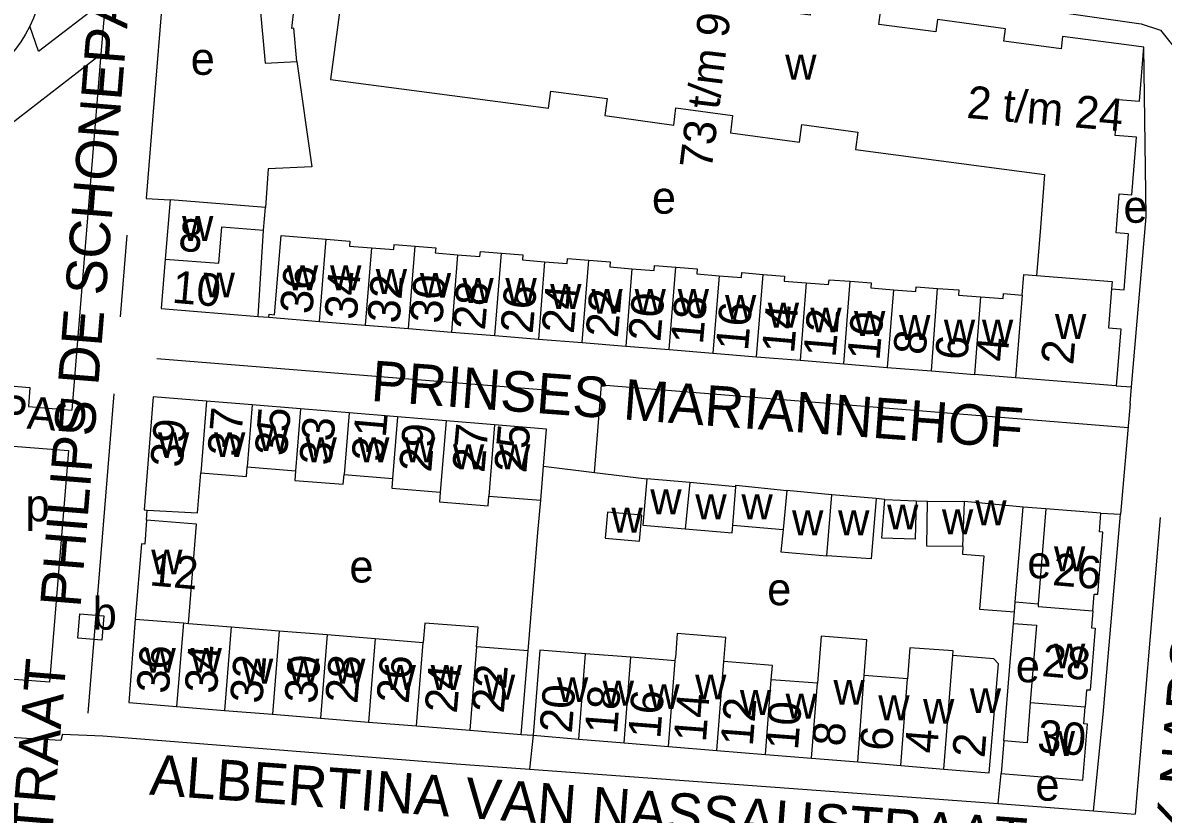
# Model space of a CAD drawing. Extents: x 159261 to 160849, y 382514 to 384534.
# Drawn here: x 160446.5 to 160587.3, y 383197.9 to 383295.6 of the extents above; entities that cross this region are included whole.
import ezdxf

# ---------------------------------------------------------------- set-up
doc = ezdxf.new("R2010")
doc.units = 0
for name, color, linetype in [('BLT_Basislijn', 7, 'Continuous'), ('BLT_Bebouwing', 7, 'Continuous'), ('BLT_Centroide', 7, 'Continuous'), ('BLT_Huisnummer', 7, 'Continuous'), ('BLT_Huisnummer_ tussenligend', 7, 'Continuous'), ('BLT_Huisnummer_reeks', 7, 'Continuous'), ('BLT_Onderverdeling_panden', 7, 'Continuous'), ('BLT_Straatnaam', 7, 'Continuous'), ('BLT_Straatnaam_verkleind', 7, 'Continuous')]:
    doc.layers.add(name, color=color, linetype=linetype)

msp = doc.modelspace()

# ---------------------------------------------------------------- linework, layer by layer
at = {"layer": 'BLT_Basislijn'}
for p, q in [((160464.45, 383307.53), (160462.73, 383286.15)), ((160448.46, 383292.15), (160456.71, 383298.51)), ((160456.71, 383298.51), (160456.16, 383291.77)), ((160568.13, 383297.86), (160584.55, 383295.5)), ((160448.46, 383292.15), (160447.37, 383295.2)), ((160430.9, 383272.29), (160456.16, 383291.77)), ((160456.16, 383291.77), (160452.56, 383247.83)), ((160480.34, 383290.85), (160482.21, 383277.84)), ((160462.73, 383286.15), (160461.75, 383273.95)), ((160461.75, 383273.95), (160464.7, 383273.78)), ((160458.56, 383259.32), (160459.39, 383269.42)), ((160475.56, 383259.39), (160476.89, 383259.28)), ((160463.05, 383254.2), (160511.51, 383250.27)), ((160581.48, 383250.8), (160583.37, 383250.69)), ((160583.19, 383248.63), (160583.37, 383250.69)), ((160454.57, 383210.42), (160457.79, 383249.85)), ((160447.21, 383248.25), (160452.56, 383247.83)), ((160583.19, 383248.63), (160582.01, 383234.97)), ((160445.32, 383243.38), (160452.15, 383242.84)), ((160452.15, 383242.84), (160449.81, 383214.26)), ((160510.78, 383240.9), (160517.07, 383240.13)), ((160517.07, 383240.13), (160523.53, 383239.33)), ((160510.09, 383232.7), (160510.44, 383236.7)), ((160552.91, 383236.79), (160551.86, 383236.9)), ((160556.8, 383236.62), (160558.18, 383236.59)), ((160461.8, 383234.23), (160461.87, 383235.47)), ((160572.8, 383235.64), (160569.98, 383235.85)), ((160579.6, 383235.09), (160582.01, 383234.97)), ((160586.91, 383234.56), (160583.82, 383197.95)), ((160508.89, 383218.1), (160510.09, 383232.7)), ((160449.81, 383214.26), (160444.34, 383214.65)), ((160446.96, 383207.29), (160443.81, 383207.5)), ((160451.4, 383207.83), (160456.41, 383207.6)), ((160508.02, 383207.79), (160509.5, 383207.69)), ((160509.5, 383207.69), (160509.04, 383203.52)), ((160509.04, 383203.52), (160566.93, 383199.26)), ((160566.93, 383199.26), (160567.3, 383202.95)), ((160566.93, 383199.26), (160578.66, 383198.35)), ((160578.66, 383198.35), (160583.82, 383197.95))]:
    msp.add_line(p, q, dxfattribs=at)
for points in [[(160448.48, 383298.32), (160448.19, 383297.25), (160447.82, 383296.21), (160447.37, 383295.2)], [(160584.55, 383295.5), (160586.95, 383294.73), (160588.92, 383292.24), (160589.56, 383290.35)], [(160447.37, 383295.2), (160446.86, 383294.22), (160446.27, 383293.28), (160445.62, 383292.38), (160444.91, 383291.54), (160444.14, 383290.75), (160443.53, 383290.2)], [(160583.37, 383250.69), (160585.18, 383271.68), (160584.88, 383292.62)], [(160482.21, 383277.84), (160476.79, 383277.6), (160476.45, 383272.82)], [(160412.58, 383255.96), (160415.4, 383253.87), (160418.04, 383253.1), (160447.4, 383250.63), (160447.21, 383248.25)], [(160517.07, 383240.13), (160517.95, 383250.95), (160582.96, 383245.67)], [(160578.66, 383198.35), (160579.88, 383210.25), (160582.01, 383234.97)], [(160567.63, 383207.01), (160568.39, 383216.72), (160568.82, 383221.5)], [(160451.4, 383207.83), (160451.19, 383207.06), (160446.96, 383207.29)], [(160456.41, 383207.6), (160500, 383204.17), (160508.54, 383203.55), (160509.04, 383203.52)]]:
    msp.add_lwpolyline(points, dxfattribs=at)
at = {"layer": 'BLT_Bebouwing'}
for p, q in [((160584.34, 383285.95), (160584.88, 383292.62)), ((160464.7, 383273.78), (160464.1, 383266.46)), ((160476.45, 383272.82), (160464.7, 383273.78)), ((160476.22, 383270.05), (160476.45, 383272.82)), ((160475.56, 383259.39), (160476.22, 383270.05)), ((160489.56, 383267.86), (160492.32, 383267.64)), ((160464.1, 383266.46), (160463.6, 383260.36)), ((160463.6, 383260.36), (160475.56, 383259.39)), ((160476.89, 383259.28), (160483.15, 383258.77)), ((160483.15, 383258.77), (160488.79, 383258.32)), ((160488.79, 383258.32), (160494.11, 383257.89)), ((160494.11, 383257.89), (160499.41, 383257.46)), ((160499.41, 383257.46), (160504.77, 383257.03)), ((160504.77, 383257.03), (160510.15, 383256.59)), ((160510.15, 383256.59), (160515.54, 383256.16)), ((160515.54, 383256.16), (160520.93, 383255.72)), ((160520.93, 383255.72), (160526.31, 383255.29)), ((160526.31, 383255.29), (160531.69, 383254.85)), ((160531.69, 383254.85), (160537.07, 383254.41)), ((160537.07, 383254.41), (160542.46, 383253.97)), ((160542.46, 383253.97), (160547.85, 383253.54)), ((160547.85, 383253.54), (160553.23, 383253.1)), ((160553.23, 383253.1), (160558.67, 383252.66)), ((160558.67, 383252.66), (160563.98, 383252.23)), ((160569.06, 383251.81), (160563.98, 383252.23)), ((160581.48, 383250.8), (160569.06, 383251.81)), ((160469.18, 383248.92), (160462.61, 383249.46)), ((160474.83, 383248.46), (160469.18, 383248.92)), ((160480.81, 383247.97), (160474.83, 383248.46)), ((160486.78, 383247.49), (160480.81, 383247.97)), ((160492.77, 383246.99), (160486.78, 383247.49)), ((160498.76, 383246.51), (160492.77, 383246.99)), ((160504.74, 383246.02), (160498.76, 383246.51)), ((160474.21, 383240.82), (160480.19, 383240.34)), ((160510.44, 383236.7), (160510.77, 383240.9)), ((160486.17, 383239.86), (160492.15, 383239.38)), ((160528.86, 383238.87), (160523.53, 383239.33)), ((160534.52, 383238.37), (160528.86, 383238.87)), ((160546.37, 383237.36), (160540.84, 383237.92)), ((160504.03, 383237.21), (160510.44, 383236.7)), ((160551.86, 383236.9), (160546.37, 383237.36)), ((160552.91, 383236.79), (160556.8, 383236.62)), ((160556.8, 383236.62), (160556.66, 383231.88)), ((160558.18, 383236.59), (160562.75, 383236.54)), ((160569.98, 383235.85), (160562.75, 383236.54)), ((160569.03, 383224.14), (160569.98, 383235.85)), ((160572.8, 383235.64), (160571.86, 383223.91)), ((160579.6, 383235.09), (160572.8, 383235.64)), ((160534.15, 383233.63), (160540.37, 383233.08)), ((160569.03, 383224.14), (160571.86, 383223.91)), ((160568.82, 383221.5), (160568.94, 383222.92)), ((160466.98, 383221.49), (160472.25, 383221.07)), ((160472.25, 383221.07), (160478.17, 383220.59)), ((160478.17, 383220.59), (160484.1, 383220.11)), ((160484.1, 383220.11), (160490.02, 383219.63)), ((160490.02, 383219.63), (160495.94, 383219.15)), ((160508.89, 383218.1), (160502.53, 383218.61)), ((160508.02, 383207.79), (160508.89, 383218.1)), ((160515.97, 383217.74), (160510.34, 383218.18)), ((160521.56, 383217.31), (160515.97, 383217.74)), ((160527.04, 383216.88), (160521.56, 383217.31)), ((160527.04, 383216.88), (160527.07, 383217.26)), ((160565.8, 383203.07), (160566.94, 383216.5)), ((160544.6, 383214.11), (160538.91, 383214.55)), ((160465.5, 383211.24), (160471.42, 383210.76)), ((160471.42, 383210.76), (160477.34, 383210.28)), ((160477.34, 383210.28), (160483.26, 383209.8)), ((160483.26, 383209.8), (160489.18, 383209.32)), ((160489.18, 383209.32), (160495.1, 383208.84)), ((160495.1, 383208.84), (160501.7, 383208.3)), ((160501.7, 383208.3), (160508.02, 383207.79)), ((160509.5, 383207.69), (160515.16, 383207.22)), ((160515.16, 383207.22), (160520.74, 383206.76)), ((160520.74, 383206.76), (160526.22, 383206.3)), ((160567.63, 383207.01), (160567.3, 383202.95)), ((160526.22, 383206.3), (160532.2, 383205.82)), ((160532.2, 383205.82), (160538.19, 383205.33)), ((160538.19, 383205.33), (160543.88, 383204.87)), ((160543.88, 383204.87), (160549.57, 383204.4)), ((160549.57, 383204.4), (160554.88, 383203.96)), ((160554.88, 383203.96), (160560.22, 383203.52)), ((160560.22, 383203.52), (160565.8, 383203.07))]:
    msp.add_line(p, q, dxfattribs=at)
for points in [[(160479.72, 383294.94), (160480.01, 383297.49), (160479.41, 383303.07), (160479.15, 383305.48)], [(160486.8, 383305.75), (160486.29, 383301.95), (160488.17, 383301.67), (160487.79, 383299.16), (160485.95, 383299.43), (160484.5, 383288.62), (160511.42, 383285.09), (160511.7, 383287.2), (160518.65, 383286.27), (160518.37, 383284.18), (160526.86, 383283.01), (160527.14, 383285.14), (160534.13, 383284.2), (160533.88, 383282.07), (160542.39, 383280.91), (160542.68, 383283.06), (160549.58, 383282.14), (160549.32, 383279.98), (160572.65, 383276.89), (160572.08, 383269.81), (160571.65, 383264.44)], [(160584.88, 383292.62), (160583.35, 383292.83), (160574.87, 383293.96), (160574.67, 383292.43), (160567.62, 383293.38), (160567.83, 383294.9), (160559.42, 383296.03), (160559.21, 383294.5), (160552.17, 383295.44), (160552.37, 383296.97), (160543.93, 383298.1), (160543.72, 383296.57), (160536.68, 383297.53), (160536.89, 383299.04), (160528.46, 383300.17), (160528.26, 383298.66), (160521.21, 383299.6), (160521.42, 383301.11), (160512.99, 383302.24), (160512.8, 383300.72), (160505.75, 383301.67), (160505.98, 383303.34), (160486.8, 383305.75)], [(160475.77, 383297.83), (160476.44, 383290.64), (160480.34, 383290.85)], [(160480.34, 383290.85), (160479.96, 383294.98), (160479.72, 383294.94)], [(160580.91, 383262.8), (160582.45, 383262.67), (160583.01, 383269.59), (160581.47, 383269.71), (160581.86, 383274.52), (160583.4, 383274.39), (160583.98, 383281.52), (160582.44, 383281.64), (160581.35, 383281.73), (160581.71, 383286.18), (160582.8, 383286.08), (160584.34, 383285.95)], [(160476.89, 383259.28), (160476.93, 383259.65), (160477.59, 383259.6), (160478.39, 383269.38), (160483.97, 383268.93)], [(160483.97, 383268.93), (160486.87, 383268.69), (160486.82, 383268.08), (160489.56, 383267.86)], [(160492.32, 383267.64), (160492.37, 383268.26), (160494.93, 383268.06)], [(160494.93, 383268.06), (160497.48, 383267.85), (160497.43, 383267.22), (160500.18, 383267)], [(160500.18, 383267), (160502.94, 383266.78), (160503, 383267.41), (160505.62, 383267.2)], [(160505.62, 383267.2), (160508.23, 383266.98), (160508.18, 383266.36), (160510.92, 383266.14)], [(160510.92, 383266.14), (160513.69, 383265.92), (160513.74, 383266.54), (160516.38, 383266.33)], [(160516.38, 383266.33), (160519.02, 383266.11), (160518.97, 383265.49), (160521.7, 383265.27)], [(160521.7, 383265.27), (160524.45, 383265.05), (160524.5, 383265.67), (160527.13, 383265.46)], [(160527.13, 383265.46), (160529.76, 383265.25), (160529.71, 383264.63), (160532.46, 383264.41)], [(160532.46, 383264.41), (160535.22, 383264.18), (160535.26, 383264.8), (160537.9, 383264.58)], [(160537.9, 383264.58), (160540.53, 383264.37), (160540.48, 383263.76), (160543.23, 383263.54)], [(160569.89, 383262.01), (160570.1, 383264.57), (160571.65, 383264.44)], [(160543.23, 383263.54), (160545.98, 383263.32), (160546.03, 383263.92), (160548.64, 383263.72)], [(160548.64, 383263.72), (160551.24, 383263.52), (160551.2, 383262.9), (160554, 383262.67)], [(160554, 383262.67), (160556.75, 383262.45), (160556.8, 383263.04), (160559.42, 383262.85)], [(160559.42, 383262.85), (160562.05, 383262.66), (160562, 383262.03), (160564.75, 383261.81)], [(160564.75, 383261.81), (160567.52, 383261.58), (160567.57, 383262.2), (160569.89, 383262.01)], [(160580.91, 383262.8), (160580.52, 383258), (160582.06, 383257.87), (160581.48, 383250.8)], [(160462.61, 383249.46), (160461.49, 383235.5), (160461.87, 383235.47)], [(160510.78, 383240.9), (160511.15, 383245.49), (160504.74, 383246.02)], [(160468.47, 383240.08), (160474.12, 383239.62), (160474.21, 383240.82)], [(160461.87, 383235.47), (160468.07, 383235.13), (160468.47, 383240.08)], [(160480.19, 383240.34), (160480.1, 383239.15), (160486.07, 383238.67), (160486.17, 383239.86)], [(160492.15, 383239.38), (160492.05, 383238.18), (160498.05, 383237.69)], [(160523.53, 383239.33), (160523.05, 383233.64), (160528.28, 383233.18)], [(160498.05, 383237.69), (160497.95, 383236.5), (160503.94, 383236.02), (160504.03, 383237.21)], [(160534.52, 383238.37), (160534.53, 383238.55), (160540.84, 383237.92)], [(160551.86, 383236.9), (160551.22, 383229.46), (160545.76, 383229.82)], [(160556.66, 383231.88), (160552.57, 383232), (160552.91, 383236.79)], [(160562.57, 383230.99), (160558.12, 383231.04), (160558.18, 383236.59)], [(160578.61, 383223.03), (160578.78, 383225.12), (160579.23, 383225.09), (160579.85, 383232.74), (160579.41, 383232.78), (160579.6, 383235.09)], [(160461.8, 383234.23), (160461.56, 383231.27), (160461.15, 383231.3), (160460.4, 383222.03)], [(160466.98, 383221.49), (160467.96, 383233.74), (160461.8, 383234.23)], [(160528.28, 383233.18), (160534.08, 383232.66), (160534.15, 383233.63)], [(160540.37, 383233.08), (160540.1, 383230.32), (160545.76, 383229.82)], [(160562.57, 383230.99), (160562.49, 383230.03), (160565.15, 383229.82), (160564.62, 383223.27), (160568.94, 383222.92)], [(160578.61, 383223.03), (160578.44, 383220.94), (160578.89, 383220.9), (160578.26, 383213.24), (160577.82, 383213.27), (160577.65, 383211.18)], [(160460.4, 383222.03), (160459.58, 383211.72), (160465.5, 383211.24)], [(160502.53, 383218.61), (160502.72, 383221.02), (160496.13, 383221.54), (160495.94, 383219.15)], [(160568.82, 383221.5), (160571.64, 383221.27), (160570.88, 383211.74)], [(160533.05, 383216.78), (160533.29, 383219.77), (160527.3, 383220.24), (160527.07, 383217.26)], [(160550.38, 383215.07), (160550.72, 383219.47), (160545.05, 383219.91), (160544.6, 383214.11)], [(160510.34, 383218.18), (160509.5, 383207.69)], [(160561.3, 383217.54), (160561.35, 383218.09), (160556.01, 383218.5), (160555.71, 383214.65)], [(160538.91, 383214.55), (160539.04, 383216.29), (160533.05, 383216.78)], [(160566.94, 383216.5), (160566.39, 383217.14), (160561.3, 383217.54)], [(160555.71, 383214.65), (160550.38, 383215.07)], [(160567.3, 383202.95), (160577.36, 383202.14), (160577.92, 383209.05), (160577.48, 383209.09), (160577.65, 383211.18)], [(160570.88, 383211.74), (160570.48, 383206.77), (160567.63, 383207.01)]]:
    msp.add_lwpolyline(points, dxfattribs=at)
for points in [[(160522.92, 383234.86), (160518.67, 383235.24), (160518.38, 383232.03), (160522.63, 383231.65)], [(160453.56, 383222.67), (160456.5, 383222.42), (160456.25, 383219.44), (160453.31, 383219.68)]]:
    msp.add_lwpolyline(points, close=True, dxfattribs=at)
at = {"layer": 'BLT_Onderverdeling_panden'}
for p, q in [((160483.15, 383258.77), (160483.97, 383268.93)), ((160489.56, 383267.86), (160488.79, 383258.32)), ((160494.11, 383257.89), (160494.93, 383268.06)), ((160504.77, 383257.03), (160505.62, 383267.2)), ((160500.18, 383267), (160499.41, 383257.46)), ((160510.92, 383266.14), (160510.15, 383256.59)), ((160515.54, 383256.16), (160516.38, 383266.33)), ((160521.7, 383265.27), (160520.93, 383255.72)), ((160526.31, 383255.29), (160527.13, 383265.46)), ((160532.46, 383264.41), (160531.69, 383254.85)), ((160537.07, 383254.41), (160537.9, 383264.58)), ((160543.23, 383263.54), (160542.46, 383253.97)), ((160547.85, 383253.54), (160548.64, 383263.72)), ((160554, 383262.67), (160553.23, 383253.1)), ((160558.67, 383252.66), (160559.42, 383262.85)), ((160564.75, 383261.81), (160563.98, 383252.23)), ((160569.89, 383262.01), (160569.06, 383251.81)), ((160469.18, 383248.92), (160468.47, 383240.08)), ((160474.83, 383248.46), (160474.21, 383240.82)), ((160480.81, 383247.97), (160480.19, 383240.34)), ((160486.78, 383247.49), (160486.17, 383239.86)), ((160492.77, 383246.99), (160492.15, 383239.38)), ((160498.76, 383246.51), (160498.05, 383237.69)), ((160504.74, 383246.02), (160504.03, 383237.21)), ((160528.86, 383238.87), (160528.28, 383233.18)), ((160534.15, 383233.63), (160534.52, 383238.37)), ((160540.84, 383237.92), (160540.37, 383233.08)), ((160545.76, 383229.82), (160546.37, 383237.36)), ((160562.57, 383230.99), (160562.75, 383236.54)), ((160568.94, 383222.92), (160569.03, 383224.14)), ((160460.4, 383222.03), (160466.33, 383221.55)), ((160466.33, 383221.55), (160465.5, 383211.24)), ((160466.33, 383221.55), (160466.98, 383221.49)), ((160472.25, 383221.07), (160471.42, 383210.76)), ((160478.17, 383220.59), (160477.34, 383210.28)), ((160484.1, 383220.11), (160483.26, 383209.8)), ((160490.02, 383219.63), (160489.18, 383209.32)), ((160495.1, 383208.84), (160495.94, 383219.15)), ((160502.53, 383218.61), (160501.7, 383208.3)), ((160515.16, 383207.22), (160515.97, 383217.74)), ((160520.74, 383206.76), (160521.56, 383217.31)), ((160526.22, 383206.3), (160527.04, 383216.88)), ((160532.2, 383205.82), (160533.05, 383216.78)), ((160560.22, 383203.52), (160561.3, 383217.54)), ((160549.57, 383204.4), (160550.38, 383215.07)), ((160538.19, 383205.33), (160538.91, 383214.55)), ((160543.88, 383204.87), (160544.6, 383214.11)), ((160554.88, 383203.96), (160555.71, 383214.65)), ((160570.88, 383211.74), (160577.65, 383211.18))]:
    msp.add_line(p, q, dxfattribs=at)
for points in [[(160464.1, 383266.46), (160470.71, 383265.98), (160471.06, 383270.45), (160476.22, 383270.05)], [(160571.65, 383264.44), (160580.98, 383263.69), (160580.91, 383262.8)], [(160571.86, 383223.91), (160571.83, 383223.58), (160578.61, 383223.03)]]:
    msp.add_lwpolyline(points, dxfattribs=at)

# ---------------------------------------------------------------- texts
at = {"layer": 'BLT_Centroide'}
for s, p in [('e', (160467.24, 383289.21)), ('w', (160540.62, 383288.63)), ('e', (160524.17, 383272.07)), ('e', (160582.38, 383270.95)), ('w', (160466.17, 383268.71)), ('w', (160468.83, 383261.73)), ('w', (160479.11, 383262.61)), ('w', (160484.44, 383262.61)), ('w', (160490.08, 383262.17)), ('w', (160495.52, 383261.69)), ('w', (160500.77, 383261.04)), ('w', (160506.09, 383261.04)), ('w', (160511.61, 383260.32)), ('w', (160516.7, 383259.71)), ('w', (160522.03, 383259.71)), ('w', (160527.35, 383259.71)), ('w', (160533.19, 383258.98)), ('w', (160538.47, 383258.01)), ('w', (160543.72, 383257.41)), ('w', (160549.12, 383256.97)), ('w', (160554.68, 383256.48)), ('w', (160560.21, 383255.93)), ('w', (160564.91, 383255.93)), ('w', (160573.93, 383256.6)), ('w', (160463.2, 383242.02)), ('w', (160470.12, 383242.02)), ('w', (160475.48, 383242.79)), ('w', (160481.41, 383241.38)), ('w', (160487.9, 383241.38)), ('w', (160493.58, 383241.38)), ('w', (160499.61, 383240.53)), ('w', (160505.3, 383240.53)), ('w', (160523.97, 383234.96)), ('p', (160446.85, 383234.09)), ('w', (160529.53, 383234.35)), ('w', (160535.22, 383234.35)), ('w', (160553.2, 383233.1)), ('w', (160564.09, 383233.62)), ('w', (160519.17, 383232.7)), ('w', (160541.47, 383232.37)), ('w', (160547.15, 383232.37)), ('w', (160559.97, 383232.5)), ('w', (160462.36, 383227.54)), ('w', (160573.8, 383227.94)), ('e', (160486.83, 383226.54)), ('e', (160570.51, 383227.06)), ('e', (160538.4, 383223.74)), ('b', (160455.14, 383220.73)), ('w', (160461.54, 383215.4)), ('w', (160467.22, 383215.4)), ('w', (160573.8, 383215.94)), ('w', (160473.56, 383214.06)), ('w', (160479.25, 383214.06)), ('w', (160484.94, 383214.06)), ('e', (160569.09, 383214.23)), ('w', (160491.17, 383213.28)), ('w', (160496.86, 383213.28)), ('w', (160503.42, 383212.08)), ('w', (160529.5, 383212.11)), ('w', (160512.45, 383211.78)), ('w', (160518.09, 383211.34)), ('w', (160523.73, 383210.91)), ('w', (160546.58, 383211.45)), ('w', (160535.03, 383210.19)), ('w', (160540.67, 383209.75)), ('w', (160552.11, 383209.55)), ('w', (160563.41, 383210.42)), ('w', (160557.64, 383209.11)), ('w', (160572.53, 383205.13)), ('e', (160571.51, 383199.61))]:
    msp.add_text(s, height=4, dxfattribs=at).set_placement(p)
at = {"layer": 'BLT_Huisnummer'}
for s, rotation, p in [('8', 355, (160465.61, 383267.52)), ('10', 355, (160464.85, 383261.09)), ('36', 85, (160482.23, 383259.6)), ('34', 85, (160487.71, 383258.89)), ('30', 85, (160498.27, 383258.42)), ('26', 85, (160509.44, 383257.18)), ('22', 85, (160519.96, 383256.67)), ('18', 85, (160530.46, 383255.86)), ('14', 85, (160541.71, 383254.74)), ('10', 85, (160552.25, 383253.86)), ('6', 85, (160563.09, 383253.9)), ('2', 85, (160576.17, 383253.33)), ('37', 85, (160473.27, 383242.02)), ('39', 85, (160466.21, 383240.65)), ('33', 85, (160484.6, 383240.91)), ('29', 85, (160496.92, 383240.08)), ('25', 85, (160508.66, 383239.98)), ('12', 355, (160462.06, 383226.2)), ('26', 355, (160573.53, 383226.23)), ('36', 85, (160464.5, 383212.74)), ('34', 85, (160470.44, 383212.74)), ('28', 355, (160572.2, 383215)), ('30', 85, (160482.76, 383211.5)), ('26', 85, (160494.13, 383211.5)), ('22', 85, (160505.88, 383210.33)), ('20', 85.5533, (160514.28, 383207.87)), ('18', 85.5533, (160519.86, 383207.75)), ('14', 85.5528, (160530.83, 383206.77)), ('10', 85.5569, (160542.2, 383205.79)), ('30', 355, (160571.64, 383205.66)), ('6', 85.5536, (160553.81, 383205.67)), ('2', 85.554, (160565.23, 383204.82))]:
    msp.add_text(s, height=4, rotation=rotation, dxfattribs=at).set_placement(p)
at = {"layer": 'BLT_Huisnummer_ tussenligend'}
for s, rotation, p in [('32', 85, (160492.99, 383258.44)), ('28', 85, (160503.55, 383257.61)), ('24', 85, (160514.52, 383257.18)), ('20', 85, (160525.21, 383256.19)), ('16', 85, (160536.02, 383255.06)), ('12', 85, (160546.83, 383254.25)), ('8', 85, (160557.93, 383254.55)), ('4', 85, (160568.04, 383253.71)), ('35', 85, (160479.1, 383242.07)), ('31', 85, (160491.05, 383241.39)), ('27', 85, (160503.49, 383240.02)), ('32', 85, (160476.05, 383211.52)), ('28', 85, (160487.8, 383211.51)), ('24', 85, (160500.08, 383210.31)), ('16', 85.5533, (160525.2, 383207.19)), ('12', 85.5569, (160536.62, 383206.26)), ('8', 85.5536, (160547.93, 383206.23)), ('4', 85.554, (160559.36, 383205.36))]:
    msp.add_text(s, height=4, rotation=rotation, dxfattribs=at).set_placement(p)
at = {"layer": 'BLT_Huisnummer_reeks'}
for s, rotation, p in [('73 t/m 95c', 83, (160531.54, 383277.45)), ('2 t/m 24', 355, (160562.93, 383283.9))]:
    msp.add_text(s, height=4, rotation=rotation, dxfattribs=at).set_placement(p)
at = {"layer": 'BLT_Straatnaam'}
for s, height, rotation, p in [('WILLEMSTRAAT', 5, 352.7092, (160572.85, 383300.88)), ('LODEWIJK NAPOLEONLAAN', 5, 85.2642, (160588.82, 383165.33)), ('PRINSES MARIANNEHOF', 4.9999, 355.7977, (160489.4, 383248.97)), ('WILLEM FRISOSTRAAT', 5, 85.305, (160445.82, 383142.82)), ('ALBERTINA VAN NASSAUSTRAAT', 4.9999, 355.7977, (160462.06, 383200.37))]:
    msp.add_text(s, height=height, rotation=rotation, dxfattribs=at).set_placement(p)
at = {"layer": 'BLT_Straatnaam_verkleind'}
for s, height, rotation, p in [('PHILIPS DE SCHONEPAD', 5, 85.398, (160453.63, 383223.37)), ('BURGEMEESTER VOGELSPAD', 4, 355.8119, (160375.2, 383250.8))]:
    msp.add_text(s, height=height, rotation=rotation, dxfattribs=at).set_placement(p)

doc.saveas('drawing.dxf')
